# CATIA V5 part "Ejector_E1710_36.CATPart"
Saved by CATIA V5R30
Part number: Vyhazovac_7x160_12
Nomenclature: E1710/7x160
Description: MEUSBURGER
Property "Material": "1.221"
Publications: "__DrillHole", "Base"
Bounding box of the stored display mesh (mm): x -5.992 to 5.992, y -5.992 to 5.992, z 0 to 152
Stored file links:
  E:\Bakalarka\Model\Forma_v7\Ejector_E1710_36.CATPart
  E:\dev\MoldDesign\intel_a\startup\components\MoldCatalog\Ejector\Meusburger\Ejector_E1710\TableE1710.txt
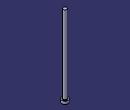
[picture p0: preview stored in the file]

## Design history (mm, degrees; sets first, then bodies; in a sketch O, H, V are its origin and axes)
Parameters
  Ref = "E1710/7x160" {design table}
  D1 = 7 mm {design table}
  D3 = 12 mm {design table}
  L = 160 mm {design table}
  L3 = 5 mm {design table}
  R = 0.5 mm {design table}
  k_d3 = 13 mm {design table}
  k_d1 = 7.2 mm {design table}
  k_F = 0.5 mm {design table}
  kl = 17 mm {design table}
  Mat = "1.221" {design table}
  HeatTreat = "ISO6751" {design table}
  Offset_Parting = 10 mm
  Anti_Rotation = "Normal"
  Anti_Rotation_D = 4 mm
  Anti_Rotation_D_Icut = 4 mm
  Add_Length_L = 1.3377 mm
  Add_Length_D3 = 0 mm
  SupplierRef = "Meusburger 2017"
  BmpRef = "F_MldEjectorD1"
  DrillHole_Length = 225 mm
  ValidationTest = false
  Anti_Rotation_D_min = 4 mm {= OffSet_D1 /2}
  Anti_Rotation_D_max = 5.925 mm {= D3/2-0.075mm}
  Anti_Rotation_D_ref = 4 mm {= Anti_Rotation_D}
  Anti_Rotation_D_Icut_ref = 4 mm {= Anti_Rotation_D_Icut}
  Anti_Rotation_Ref_Icut = 2.3246 mm
  Offset_L = 20 mm
  D = 7 mm {= D1}
  OffSet_D1 = 8 mm {= D1+2*R}
  OffSet_D3 = 13 mm {= D3+1mm}
  XG_Split = 125.5 mm
  YG_Split = -45 mm
  ZG_Split = -198 mm
  DirX_Split = 0 mm
  DirY_Split = 0 mm
  DirZ_Split = 1 mm
Set1 "BaseBody"
  Point1 "Base": (0, 0, 0)
  Plane1: type Offset, RefPlane xy-plane, Offset 225 {= DrillHole_Length}, reversed
  Sketch1 "Sketch.2" on xy-plane, origin (0, 0, 0), H (1, 0, 0), V (0, 1, 0)
    point P1 (-0.46, 1.1623)
    point P2 (0.46, 1.1623)
    construction line L1 (-0.46, 1.1623) -> (0.46, 1.1623)
    point P3 (0.46, -1.1623)
    line L2 (0.46, -1.1623) -> (0.46, 1.1623)
    point P4 (-0.46, -1.1623)
    construction line L3 (0.46, -1.1623) -> (-0.46, -1.1623)
    line L4 (-0.46, 1.1623) -> (-0.46, -1.1623)
    point P5 (-0.21, 1.1623)
    arc A1 centre (-0.21, 1.1623) radius 0.25 from (-0.21, 1.4123) to (-0.46, 1.1623) ccw
    point P7 (0.21, 1.1623)
    point P8 (0.21, 1.4123)
    arc A2 centre (0.21, 1.1623) radius 0.25 from (0.46, 1.1623) to (0.21, 1.4123) ccw
    line L5 (-0.21, 1.4123) -> (0.21, 1.4123)
    point P9 (-0.46, -1.1623)
    arc A3 centre (-0.21, -1.1623) radius 0.25 from (-0.46, -1.1623) to (-0.21, -1.4123) ccw
    point P11 (0.21, -1.4123)
    line L6 (-0.21, -1.4123) -> (0.21, -1.4123)
    point P12 (0.46, -1.1623)
    arc A4 centre (0.21, -1.1623) radius 0.25 from (0.21, -1.4123) to (0.46, -1.1623) ccw
    point P14 (-0.46, 1.1623)
    point P15 (-0.46, -1.1623)
    point P16 (0.46, 1.1623)
    point P17 (0.46, -1.1623)
    reference projected circle E1 centre (0, 0) radius 1.25 from edge [face of Shaft1 from Sketch2.L3 | face of Shaft1 from Sketch2.L4]
    reference projected circle E2 centre (0, 0) radius 1.25 from edge [face of Shaft1 from Sketch2.L3 | face of Shaft1 from Sketch2.L4]
    reference projected circle E3 centre (0, 0) radius 1.25 from edge [face of Shaft1 from Sketch2.L3 | face of Shaft1 from Sketch2.L4]
    reference projected circle E4 centre (0, 0) radius 1.25 from edge [face of Shaft1 from Sketch2.L3 | face of Shaft1 from Sketch2.L4]
    point P18 (-0.46, -1.1623)
    point P19 (-0.21, -1.4123)
    point P20 (0.21, -1.4123)
    point P21 (0.46, -1.1623)
    point P22 (-0.21, -1.4123)
    point P23 (0.21, -1.4123)
    distance P14 P15 = 2.3246 (reference)
    distance P16 P17 = 2.3246 (reference)
    distance L1 P14 = 0 (reference)
    radius A1 = 3.5
    distance L4 V = 4.01
    distance L2 V = 5.935
    distance L5 L6 = 12
    horizontal: L1 H, L3 H, L5 H
    vertical: L2 V, L4 V
    coincidence: P5 L1, P7 L1, P3 P12, P14 L4, P15 L4, P16 L2, P17 L2, P14 E1, P15 E2, P16 E3, P17 E4, P3 P21, P4 P18, P20 P23, P19 P22
    tangency: A1 L4, A2 L2, A2 L5, A1 L5
    symmetry: P1 P9 H, A1 A3 H, P8 P11 H, L5 L6 H, P2 P12 H, A2 A4 H
  DatumSurface1
Body1 "PartBody" (main body)
  Sketch2 "Sketch.1" on zx-plane, origin (0, 0, 0), H (-1, 0, 0), V (0, 0, 1)
    point P1 (0, 160)
    line L1 (3.5, 160) -> (0, 160)
    line L2 (3.5, 5) -> (3.5, 160)
    line L3 (6, 5) -> (3.5, 5)
    line L4 (6, 0) -> (6, 5)
    point P5 (0, 0)
    line L5 (0, 0) -> (6, 0)
    point P6 (0, 160)
    axis line L6 (0, 160) -> (0, 0)
    point P7 (0, 0)
    point P8 (3.5, 5)
    point P9 (3.5, 5)
    line L7 (0, 160) -> (0, 0)
    distance L5 L3 = 5 {= L3}
    distance L5 L1 = 160 {= L}
    distance L2 L6 = 3.5 {= D1 /2}
    distance L4 L6 = 6 {= D3 /2}
    coincidence: L6 P5, P1 L6, L5 H, L6 V, P7 O, P6 P1, P8 P9
    vertical: L2 V, L7 V
    horizontal: L1 H
  Shaft1 "Shaft.1": profile Sketch2, axis Sketch2.L6, angle 360
  Pocket1 "Pocket.1": profile Sketch1, direction (0, 0, 1), length 6, outer side, deactivated
  Pocket2 "Pocket.2": profile Sketch1, direction (0, 0, 1), length 6, outer side, deactivated
  Fillet1: radius 0.5 {= R}, on edge [face of Shaft1 from Sketch2.L2 | face of Shaft1 from Sketch2.L3]
  Pocket3: profile face of Shaft1 from Sketch2.L1, direction along face of Shaft1 from Sketch2.L1 reversed, up to face of DatumSurface1
Body2 "__DrillHole"
  Sketch3 "Sketch.3" on face of Shaft1, origin (0, 0, 0), H (1, 0, 0), V (0, -1, 0)
    point P1 (0, 0)
    reference projected point E1 (0, 0) from Point1
    coincidence: E1 P1
  Hole1 "Hole.1": placed by Sketch3, at (0, 0, 0) direction (0, 0, 1), diameter 8 {= OffSet_D1}, depth 140 {= L-Offset_L}
  Sketch4 "Sketch.4" on face of Shaft1, origin (0, 0, 0), H (1, 0, 0), V (0, -1, 0)
    point P1 (0, 0)
    reference projected point E1 (0, 0) from Point1
    coincidence: E1 P1
  Hole2 "Hole.2": placed by Sketch4, at (0, 0, 0) direction (0, 0, 1), diameter 7 {= D1}, depth 160 {= L}
  Sketch5 "Sketch.5" on face of Shaft1 from Sketch2.L3, origin (0, 0, 5), H (1, 0, 0), V (0, 1, 0)
    point P1 (0, 0)
    reference projected point E1 (0, 0) from Point1
    coincidence: E1 P1
  Hole3 "Hole.3": placed by Sketch5, at (0, 0, 5) direction (0, 0, -1), diameter 13 {= OffSet_D3}, depth 230 {= L3 +DrillHole_Length}
  Chamfer1: length 0.5 {= k_F}, angle 45, on edge [face of Hole1 | face of Hole3]
  Body3 "__Body.1"
    Pocket4 "Pocket.3": profile Sketch1, direction (0, 0, -1), length 225, opposite side length 5, deactivated
  Assemble1: tool Body3
  Chamfer2: length 0.5 {= k_F}, angle 45, on edge [start face of Pocket4 | face of Hole1], deactivated
  Body4 "__Body.2"
    Pocket5 "Pocket.4": profile Sketch1, direction (0, 0, -1), length 225, opposite side length 5, deactivated
  Assemble2: tool Body4
  Chamfer3: length 0.5 {= k_F}, angle 45, on edge [start face of Pocket5 | face of Hole1], deactivated
Relations
  design table "TableE1710", configuration 278, drives Ref, D1, D3, L, L3, R, k_d3, k_d1, k_F, kl, Mat, HeatTreat
  Offset_L = 20mm (deactivated)
  rule "Cut_Head_rule":
    let sketch_cut (length)
    let PartBody_Pocket_Sketch (Boolean)
    let I_PartBody_Pocket (Boolean)
    let D_PartBody_Pocket (Boolean)
    let N_DrillHole_Hole (Boolean)
    let N_DrillHole_Hole_Sketch (Boolean)
    let I_DrillHole_Pocket (Boolean)
    let D_DrillHole_Pocket (Boolean)
    /* --------------------------------------------------------------------------------------*/
    if Anti_Rotation =="Normal"
    {
    	sketch_cut=Anti_Rotation_D_max
    	PartBody_Pocket_Sketch = false
    	I_PartBody_Pocket = false
    	D_PartBody_Pocket = false
    	N_DrillHole_Hole = true
    	N_DrillHole_Hole_Sketch = true
    	I_DrillHole_Pocket = false
    	D_DrillHole_Pocket = false
    	Chamfer1.Activity= true
    	Chamfer2.Activity= false
    	Chamfer3.Activity= false
    }
    if Anti_Rotation == "I_Cut"
    {
    	sketch_cut=Anti_Rotation_D_Icut_ref
    	PartBody_Pocket_Sketch = true
    	I_PartBody_Pocket = true
    	D_PartBody_Pocket = false
    	N_DrillHole_Hole = false
    	N_DrillHole_Hole_Sketch = false
    	I_DrillHole_Pocket = true
    	D_DrillHole_Pocket = false
    	Chamfer1.Activity= false
    	Chamfer2.Activity= true
    	Chamfer3.Activity= false
    }
    if Anti_Rotation =="D_Cut"
    {
    	sketch_cut=Anti_Rotation_D_max
    	PartBody_Pocket_Sketch = true
    	I_PartBody_Pocket = false
    	D_PartBody_Pocket = true
    	N_DrillHole_Hole = false
    	N_DrillHole_Hole_Sketch = false
    	I_DrillHole_Pocket = false
    	D_DrillHole_Pocket = true
    	Chamfer1.Activity= false
    	Chamfer2.Activity= false
    	Chamfer3.Activity= true
    }
    /* --------------------------------------------------------------------------------------*/
    Sketch1.distance(L2 V) = sketch_cut+0.01mm
    Sketch1.distance(L4 V) =Anti_Rotation_D_ref+0.01mm
    Sketch1.radius(A1) =D/2
    Pocket4.FirstLimit.Depth = DrillHole_Length
    Pocket5.FirstLimit.Depth = DrillHole_Length
    Pocket1.FirstLimit.Depth = L3+1mm
    Pocket2.FirstLimit.Depth = L3+1mm
    Pocket4.SecondLimit.Depth = L3
    Pocket5.SecondLimit.Depth =L3
    Pocket1.Activity = I_PartBody_Pocket
    Pocket2.Activity = D_PartBody_Pocket
    Sketch1.Activity =PartBody_Pocket_Sketch
    Hole3.Activity= N_DrillHole_Hole
    Sketch5.Activity = N_DrillHole_Hole_Sketch
    Pocket4.Activity = I_DrillHole_Pocket
    Pocket5.Activity  = D_DrillHole_Pocket
  rule "Anti_Rotation_Icut_constrain":
    let Ref1(length)
    let Ref2(length)
    let Ref3(length)
    let Diam1(length)
    let Diam2(length)
    let Add_Length_Lmin (length)
    Ref1=Sketch1.distance(P14 P15)
    Ref2=Sketch1.distance(P16 P17)
    Diam1=D
    Diam2=D3
    /* --------------------------------------------------------------------*/
    if Ref1 >Ref2
    	Anti_Rotation_Ref_Icut = Ref1
    else
    	Anti_Rotation_Ref_Icut  =Ref2
    Add_Length_D3 .InferiorRange=Anti_Rotation_Ref_Icut /2+Diam1/2 -Diam2/2
    if Add_Length_D3 .InferiorRange<0mm
    	Add_Length_D3 .InferiorRange=0mm
    if ValidationTest == "true"
    	Ref3   = 2*Add_Length_L +Anti_Rotation_Ref_Icut  +2*Diam1/2
    else
    	Ref3  =Diam2+2*Add_Length_D3
    if Ref3 <Diam2
    {
    	Ref3 =Diam2
    }
    /* --------------------------------------------------------------------*/
    Sketch1.distance(L5 L6) = Ref3
    Add_Length_L .InferiorRange=Diam2/2-Anti_Rotation_Ref_Icut/2-Diam1/2
    Add_Length_Lmin=Diam2/2-Anti_Rotation_Ref_Icut/2-Diam1/2
    if Add_Length_Lmin<0mm
    	Add_Length_L .InferiorRange=0mm
    else
    	Add_Length_L .InferiorRange=Add_Length_Lmin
